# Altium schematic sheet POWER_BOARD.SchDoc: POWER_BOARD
size A4; Date: Not used; ApprovedBy: Not used; CheckedBy: Not used; Author: Not used; CompanyName: STMicroelectronics; DrawnBy: Not used; Engineer: Not used; Organization: Not used; Address1: Not used; Address2: Not used; Address3: Not used; Address4: Not used; DocumentNumber: 6; Revision: Not used; SheetNumber: 6; SheetTotal: 9
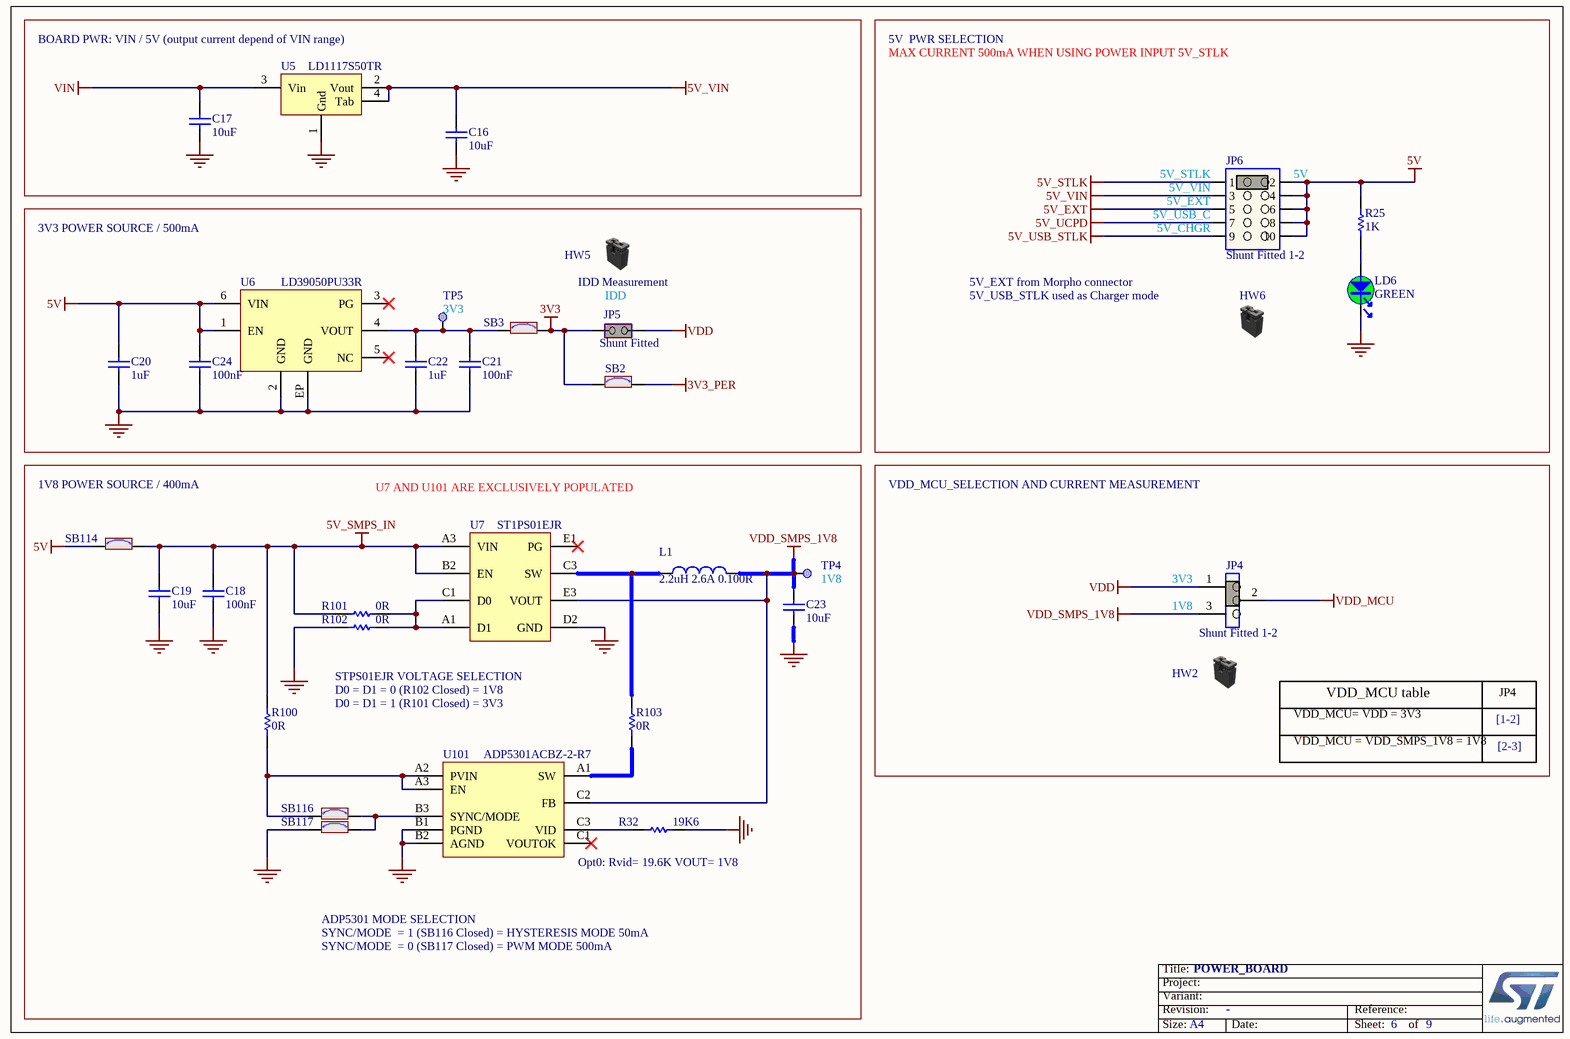
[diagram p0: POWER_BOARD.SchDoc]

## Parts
C16  value 10uF  [C0805]
C17  value 10uF  [C0805]
C18  value 100nF  [C0603]
C19  value 10uF  [C0603]
C20  value 1uF  [C0603]  (hidden comment: Capacitor)
C21  value 100nF  [C0603]
C22  value 1uF  [C0603]  (hidden comment: Capacitor)
C23  value 10uF  [C0603]
C24  value 100nF  [C0603]
HW2  (no value)  (mechanical)
HW5  (no value)  (mechanical)
HW6  (no value)  (mechanical)
JP4  value Shunt Fitted 1-2  [CON_SAMTEC_TSW-103-07-F-S]
JP5  value Shunt Fitted  [CON_SAMTEC_TSW-102-07-G-S]
JP6  value Shunt Fitted 1-2  [CON_SAMTEC_TSW-105-07-X-D]
L1  value 2.2uH 2.6A 0.100R  [IND_TDK_VLS252010HBX-1]
LD6  value GREEN  [LED_0603_GREEN]
R25  value 1K  [R0603]
R32  value 19K6  [R0603]
R100  value 0R  [R0603]
R101  value 0R  [R0603]
R102  value 0R  [R0603]
R103  value 0R  [R0603]
SB2  (no value)  [SOLDER-BRIDGE_R0603-0R]
SB3  (no value)  [SOLDER-BRIDGE_R0603-0R]
SB114  (no value)  [SOLDER-BRIDGE_R0603-0R]
SB116  (no value)  [SOLDER-BRIDGE_R0603-0R]
SB117  (no value)  [SOLDER-BRIDGE_R0603-0R]
TP4  (no value)  [TP_SMD_1MM]  (no BOM)
TP5  (no value)  [TP_SMD_1MM]  (no BOM)
U5  value LD1117S50TR  [REG_SOT223-TAB]
U6  value LD39050PU33R  [ICC_DFN6-EPAD_3X3_P095]
U7  value ST1PS01EJR  [ICC_FLIP-CHIP-BGA8_1P11X1P41_P040]
U101  value ADP5301ACBZ-2-R7  [ICC_WLCSP9_1P65X1P87_P050]

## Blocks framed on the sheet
BOARD PWR: VIN / 5V (output current depend of VIN range): C16 C17 U5
VDD_MCU table: HW2 JP4

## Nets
3V3: JP5.1(COMMON) SB2.1 SB3.2
3V3_PER: SB2.2
5V: C20.2 C24.2 JP6.2 JP6.4 JP6.6 JP6.8 JP6.10 R25.2 SB114.1 U6.1(EN) U6.6(VIN)
5V_EXT: JP6.5
5V_SMPS_IN: C18.2 C19.2 R100.1 R101.2 SB114.2 U7.A3(VIN) U7.B2(EN)
5V_STLK: JP6.1
5V_UCPD: JP6.7
5V_USB_STLK: JP6.9
5V_VIN: C16.2 JP6.3 U5.2(Vout) U5.4(Tab)
GND: C16.1 C17.1 C18.1 C19.1 C20.1 C21.1 C22.1 C23.1 C24.1 LD6.2 R32.2 R102.2 SB117.1 U5.1(Gnd) U6.2(GND) U6.EP(GND) U7.D2(GND) U101.B1(PGND) U101.B2(AGND)
VDD: JP4.1 JP5.2(NO)
VDD_MCU: JP4.2
VDD_SMPS_1V8: C23.2 JP4.3 L1.2 TP4.1 U7.E3(VOUT) U101.C2(FB)
VIN: C17.2 U5.3(Vin)
NetC21_2: C21.2 C22.2 SB3.1 TP5.1 U6.4(VOUT)
NetL1_1: L1.1 R103.1 U7.C3(SW)
NetLD6_1: LD6.1 R25.1
NetR32_1: R32.1 U101.C3(VID)
NetR100_2: R100.2 SB116.1 U101.A2(PVIN) U101.A3(EN)
NetR101_1: R101.1 R102.1 U7.A1(D1) U7.C1(D0)
NetR103_2: R103.2 U101.A1(SW)
NetSB116_2: SB116.2 SB117.2 U101.B3(SYNC/MODE)

Not connected (* = marked no-connect by the designer): U6 3(PG)* 5(NC)*; U7 E1(PG)*; U101 C1(VOUTOK)*

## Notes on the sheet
- 5V  PWR SELECTION
- MAX CURRENT 500mA WHEN USING POWER INPUT 5V_STLK
- (near JP6) 5V_STLK
- (near JP6) 5V
- 3V3 POWER SOURCE / 500mA
- (near JP6) 5V_CHGR
- (near JP6) 5V_VIN
- (near JP6) 5V_EXT
- (near JP6) 5V_USB_C
- (near TP5) 3V3
- IDD Measurement
- (near JP5) IDD
- 5V_EXT from Morpho connector
- 5V_USB_STLK used as Charger mode
- 1V8 POWER SOURCE / 400mA
- U7 AND U101 ARE EXCLUSIVELY POPULATED
- VDD_MCU_SELECTION AND CURRENT MEASUREMENT
- (near TP4) 1V8
- (near JP4) 3V3
- 1V8
- STPS01EJR VOLTAGE SELECTION
  D0 = D1 = 0 (R102 Closed) = 1V8
  D0 = D1 = 1 (R101 Closed) = 3V3
- VDD_MCU= VDD = 3V3
- [1-2]
- JP4
- VDD_MCU = VDD_SMPS_1V8 = 1V8
- [2-3]
- Opt0: Rvid= 19.6K VOUT= 1V8
- ADP5301 MODE SELECTION
  SYNC/MODE  = 1 (SB116 Closed) = HYSTERESIS MODE 50mA
  SYNC/MODE  = 0 (SB117 Closed) = PWM MODE 500mA

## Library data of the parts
C16 C17 = MCD-00014: Capacitor, MLCC, 10uF, 25V, X5R, 10%, 0805, T=0,85mm; Manufacturer_Part_Number: CC0805KRX5R8BB106; Manufacturer: YAGEO; Provided_By: Subcon; Initial_Board_Reference: MB1274
C18 C21 C24 = MCD-00211: Capacitor, MLCC, 100nF, 16V, X7R, 10%, 0603, T=0,8mm; Manufacturer_Part_Number: CC0603KRX7R7BB104; Manufacturer: YAGEO; Provided_By: Subcon; Initial_Board_Reference: MB1319
C19 C23 = MCD-00243: Capacitor, MLCC, 10uF, 6V3, X5R, 10%, 0603, T=0,8mm; Manufacturer_Part_Number: CC0603KRX5R5BB106; Manufacturer: YAGEO; Provided_By: Subcon; Initial_Board_Reference: MB1319
C20 C22 = MCD-00010: Capacitor, MLCC, 1uF, 16V, X5R, 10%, 0603, T=0,8mm; Manufacturer_Part_Number: CC0603KRX5R7BB105; Manufacturer: YAGEO; Provided_By: SUBCO
HW2 HW5 HW6 = MCD-00043: SHUNT 2.54mm BLACK; Manufacturer_Part_Number: SNT-100-BK-G; Manufacturer: SAMTEC; Part_Type: Mechanical; Provided_By: Subcon; Initial_Board_Reference: MB1274
JP4 = MCD-00684: Header, 3x1, 2,54mm, VR, TH, Height 5.84mm/2.54mm - Shunt Fitted 1-2 by default; Part_Type: Connector; Manufacturer_Part_Number: TSW-103-07-F-S; Manufacturer: SAMTEC; Provided_By: Subcon; Initial_Board_Reference: MB1331
JP5 = MCD-00683: Header, 2x1, 2,54mm, VR, TH, Height 5.84mm/2.54mm - Shunt Fitted by default; Part_Type: Connector; Manufacturer_Part_Number: TSW-102-07-x-S; Manufacturer: SAMTEC; Provided_By: Subcon; Initial_Board_Reference: MB1331
JP6 = MCD-01203: Header, 5x2, 2,54mm, VR, TH, Height 5.84mm/2.54mm - Shunt Fitted 1-2; Part_Type: Connector; Manufacturer_Part_Number: TSW-105-07-x-D; Manufacturer: SAMTEC; Provided_By: Subcon; Initial_Board_Reference: Mb1372
L1 = MCD-00240: FIXED IND 2.2UH 2.6A 100 mOHM 20% SMD; Manufacturer_Part_Number: VLS252010HBX-2R2M-1; Manufacturer: TDK; Provided_By: Subcon; Initial_Board_Reference: MB1319
LD6 = MCD-00050: LED, Green, 0603; Manufacturer_Part_Number: 19-213SYGC/S530-E2/TR8; Manufacturer: EVERLIGHT; Part_Type: Display; ECCN_US: EAR99; ECCN_EU: NEC; Provided_By: Subcon; Initial_Board_Reference: MB1274
R25 = MCD-00070: Resistor,1K,0603,1%,1/10W; Manufacturer_Part_Number: RC0603FR-071KL; Manufacturer: YAGEO; Provided_By: Subcon; Initial_Board_Reference: MB1274
R32 = MCD-00242: Resistor,19K6,0603,1%,1/10W; Manufacturer_Part_Number: RC0603FR-0719K6L; Manufacturer: YAGEO; Provided_By: Subcon; Initial_Board_Reference: MB1319
R100-R103 = MCD-00056: Resistor,0R,0603,5%,1/10W; Manufacturer_Part_Number: RC0603JR-070RL; Manufacturer: YAGEO; Provided_By: subcon; Initial_Board_Reference: MB1274
SB2 SB3 SB114 SB116 SB117 = MCD-00071: Solder Bridge ON; Part_Type: Mechanical; Provided_By: Subcon; Initial_Board_Reference: MB1274
TP4 TP5 = MCD-00074: Test Point 1mm; Part_Type: Mechanical; Initial_Board_Reference: MB1274
U5 = MCD-00088: IC REG LDO 5V 0.8A SOT223; Manufacturer: STMICROELECTRONICS; ECCN_US: EAR99; ECCN_EU: NEC; Provided_By: Subcon; Initial_Board_Reference: MB1274
U6 = MCD-00215: Low quiescent current and low noise voltage regulators; Manufacturer: STMICROELECTRONICS; Part_Type: IC; ECCN_US: EAR99; ECCN_EU: NEC; Provided_By: Subcon; Initial_Board_Reference: MB1319
U7 = MCD-00228: 400mA Nano-Quiescent Step down converter; Manufacturer: STMICROELECTRONICS; Part_Type: IC; ECCN_US: EAR99; ECCN_EU: NEC; Provided_By: Subcon; Initial_Board_Reference: MB1319
U101 = MCD-00226: UL Step down regulator: Opt0; Manufacturer: ANALOG DEVICES; Part_Type: IC; ECCN_US: EAR99; ECCN_EU: NEC; Provided_By: Subcon; Initial_Board_Reference: MB1319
